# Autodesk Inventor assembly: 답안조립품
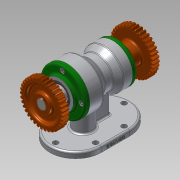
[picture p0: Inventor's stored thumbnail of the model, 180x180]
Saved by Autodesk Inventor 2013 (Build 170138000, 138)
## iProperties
Created: 2020-01
Part Number: 답안조립품
Document SubType Name: Assembly
Designer: Administrator
Author: Administrator
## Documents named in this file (13)
- C:\Users\Administrator\Desktop\700104V1022\답안조립품.iam
- C:\Users\Administrator\Desktop\700104V1022\본체.ipt
- C:\Users\Administrator\Desktop\700104V1022\뒤커버.ipt
- C:\Users\Administrator\Desktop\700104V1022\멈춤나사 M3.ipt
- C:\Users\Administrator\Desktop\700104V1022\베어링 6203.ipt
- C:\Users\Administrator\Desktop\700104V1022\베어링 6205.ipt
- C:\Users\Administrator\Desktop\700104V1022\볼트 M4.ipt
- C:\Users\Administrator\Desktop\700104V1022\스퍼기어.ipt
- C:\Users\Administrator\Desktop\700104V1022\앞커버.ipt
- C:\Users\Administrator\Desktop\700104V1022\오일 실 17 30 8.ipt
- C:\Users\Administrator\Desktop\700104V1022\오일 실 25 38 8.ipt
- C:\Users\Administrator\Desktop\700104V1022\축.ipt
- C:\Users\Administrator\Desktop\700104V1022\키 5 x 5 x 18.ipt
